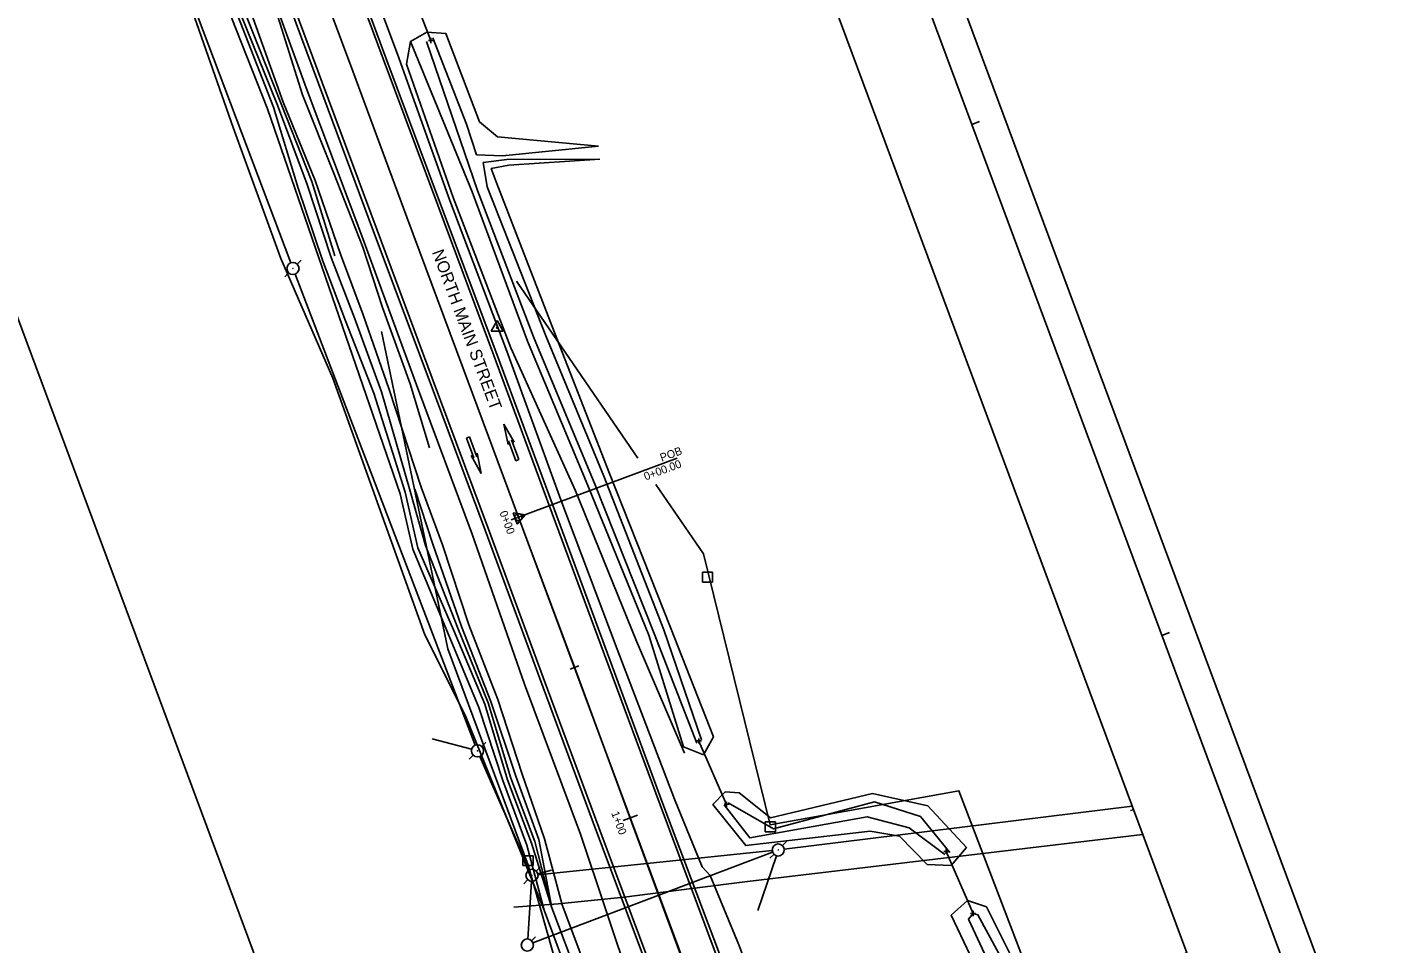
# Model space of a CAD drawing. Extents: x 1040172 to 1040822, y 1127790 to 1128580.
# Drawn here: x 1040398.7 to 1040821.5, y 1128002.5 to 1128288.4 of the extents above; entities that cross this region are included whole.
import ezdxf

# ---------------------------------------------------------------- set-up
doc = ezdxf.new("R2010")
doc.units = 0
for name, color, linetype in [('AC_P', 7, 'Continuous'), ('ACP_P', 7, 'Continuous'), ('ACSC_P_T', 7, 'Continuous'), ('ACSCT_P', 7, 'Continuous'), ('ACSR_P_T', 7, 'Continuous'), ('ACSRT_P', 7, 'Continuous'), ('CBP', 7, 'Continuous'), ('clip boundary', 7, 'Continuous'), ('DCP', 7, 'Continuous'), ('DD', 7, 'Continuous'), ('Default', 7, 'Continuous'), ('DELB', 7, 'Continuous'), ('DINV', 7, 'Continuous'), ('LABL', 7, 'Continuous'), ('LELB', 7, 'Continuous'), ('MHB', 7, 'Continuous'), ('MPM', 7, 'Continuous'), ('O_Details_Text Title and Subtitle Proposed_P_T', 7, 'Continuous'), ('PE', 7, 'Continuous'), ('RDU', 7, 'Continuous'), ('SHEET_BORDER', 7, 'Continuous'), ('SHEET_BORDER_CUT', 7, 'Continuous'), ('STPBY', 7, 'Continuous'), ('STSEW', 7, 'Continuous'), ('STSEY_P_T', 7, 'Continuous'), ('UEO', 7, 'Continuous'), ('UFO', 7, 'Continuous'), ('UP', 7, 'Continuous'), ('UPGW', 7, 'Continuous')]:
    doc.layers.add(name, color=color, linetype=linetype)

msp = doc.modelspace()

# ---------------------------------------------------------------- linework, layer by layer
at = {"layer": 'AC_P'}
msp.add_line((1040551.95, 1128135.59), (1040621.67, 1127948.13), dxfattribs=at)
at = {"layer": 'ACP_P'}
msp.add_circle((1040551.95, 1128135.59), 1.09, dxfattribs=at)
at = {"layer": 'ACSCT_P'}
msp.add_lwpolyline([(1040551.95, 1128135.59), (1040601.44, 1128153.99)], dxfattribs=at)
at = {"layer": 'ACSRT_P'}
for points in [[(1040554.2, 1128136.43), (1040549.7, 1128134.75)], [(1040570.73, 1128089.23), (1040568.03, 1128088.22)], [(1040589.06, 1128042.7), (1040584.56, 1128041.02)]]:
    msp.add_lwpolyline(points, dxfattribs=at)
at = {"layer": 'CBP'}
for points in [[(1040545.33, 1128196.91), (1040543.44, 1128193.64)], [(1040547.22, 1128193.64), (1040545.33, 1128196.91)], [(1040543.44, 1128193.64), (1040547.22, 1128193.64)]]:
    msp.add_lwpolyline(points, dxfattribs=at)
msp.add_circle((1040545.33, 1128194.73), 0.226, dxfattribs=at)
at = {"layer": 'clip boundary'}
for points in [[(1040584.48, 1128580.33), (1040821.52, 1127942.99), (1040409.12, 1127789.61), (1040172.08, 1128426.95)], [(1040311.42, 1128424.61), (1040504.79, 1127904.67), (1040760.34, 1127999.71), (1040566.96, 1128519.66)]]:
    msp.add_lwpolyline(points, close=True, dxfattribs=at)
at = {"layer": 'DCP'}
for p, q in [((1040516.73, 1128304.75), (1040524.64, 1128284.21)), ((1040608.2, 1128065.79), (1040616.86, 1128046.03)), ((1040685.33, 1128031.32), (1040693.73, 1128012))]:
    msp.add_line(p, q, dxfattribs=at)
at = {"layer": 'DD'}
msp.add_lwpolyline([(1040590.16, 1127936.41), (1040584.34, 1127954.8), (1040577.73, 1127972.42), (1040570.66, 1127991.71), (1040562.32, 1128013.81), (1040557.05, 1128034.44), (1040549.61, 1128054.25), (1040542.46, 1128077.69), (1040533.08, 1128100.98), (1040522.95, 1128126.72), (1040518.21, 1128143.72), (1040509.19, 1128174.67), (1040500.96, 1128197.49), (1040493.5, 1128216.61), (1040486.01, 1128239.31), (1040476.77, 1128264.06), (1040465.21, 1128292.91), (1040456.76, 1128312.61), (1040439.7, 1128341.45), (1040438.14, 1128345.77)], dxfattribs=at)
at = {"layer": 'Default'}
for points in [[(1040550.27, 1128136.98), (1040553.99, 1128136.35)], [(1040551.58, 1128133.44), (1040550.27, 1128136.98)], [(1040553.99, 1128136.35), (1040551.58, 1128133.44)]]:
    msp.add_lwpolyline(points, dxfattribs=at)
at = {"layer": 'DELB'}
for points in [[(1040609.63, 1128061.49), (1040603.4, 1128063.98), (1040592.64, 1128098.78), (1040573.56, 1128145.43), (1040554.77, 1128190.47), (1040537.48, 1128237.06), (1040518.28, 1128283.96), (1040523.35, 1128286.88)], [(1040576.87, 1128251.3), (1040545.4, 1128254.16), (1040539.75, 1128258.84), (1040529.3, 1128286.38), (1040523.35, 1128286.88)], [(1040576.87, 1128251.3), (1040546.97, 1128248.3), (1040538.91, 1128248.59), (1040535.75, 1128258.16), (1040525.25, 1128285.12)], [(1040607.56, 1128065.08), (1040594.26, 1128099.34), (1040575.72, 1128145.85), (1040556.63, 1128191.81), (1040539.21, 1128237.42), (1040523.27, 1128283.9)], [(1040609.07, 1128066.11), (1040597.28, 1128100.44), (1040578.59, 1128148.35), (1040560.51, 1128192.11), (1040542.16, 1128238.57), (1040540.96, 1128246.16), (1040548.27, 1128247.16), (1040577.32, 1128247.25)], [(1040609.63, 1128061.49), (1040612.73, 1128067.12), (1040599.32, 1128101.21), (1040580.32, 1128149.25), (1040563.23, 1128193.19), (1040545.04, 1128240.22), (1040543.44, 1128244.32), (1040548.97, 1128245.37), (1040577.32, 1128247.25)], [(1040686.92, 1128026.98), (1040679.43, 1128027.24), (1040670.73, 1128036.09), (1040661.62, 1128037.68), (1040622.81, 1128033.18), (1040612.58, 1128046.02), (1040616.37, 1128049.95)], [(1040686.92, 1128026.98), (1040691.64, 1128032.57), (1040679.65, 1128045.57), (1040662.38, 1128049.4), (1040630.53, 1128041.88), (1040620.82, 1128049.59), (1040616.37, 1128049.95)], [(1040684.93, 1128030.41), (1040673.79, 1128038.73), (1040660.7, 1128042.19), (1040624.06, 1128035.63), (1040616.15, 1128045.92)], [(1040686.46, 1128031.07), (1040677.28, 1128042.28), (1040663, 1128046.83), (1040631.45, 1128038.39), (1040617.38, 1128046.55)], [(1040702.66, 1127978.26), (1040686.91, 1128011.53), (1040691.97, 1128016.01), (1040697.9, 1128014.08), (1040712.9, 1127984.14), (1040713.54, 1127982.3)], [(1040706.5, 1127979.69), (1040692.31, 1128010.21), (1040693.73, 1128012), (1040695.25, 1128011.56), (1040710.7, 1127983.05), (1040711.25, 1127981.45)]]:
    msp.add_lwpolyline(points, dxfattribs=at)
at = {"layer": 'DINV'}
for p, q in [((1040524.66, 1128284.25), (1040524.66, 1128285.04)), ((1040524.66, 1128284.25), (1040523.87, 1128284.25)), ((1040524.66, 1128284.25), (1040525.44, 1128284.25)), ((1040524.66, 1128284.25), (1040524.66, 1128283.46)), ((1040608.22, 1128065.82), (1040607.43, 1128065.82)), ((1040608.22, 1128065.82), (1040608.22, 1128066.61)), ((1040608.22, 1128065.82), (1040609, 1128065.82)), ((1040608.22, 1128065.82), (1040608.22, 1128065.04)), ((1040616.87, 1128046.06), (1040616.09, 1128046.06)), ((1040616.87, 1128046.06), (1040616.87, 1128046.85)), ((1040616.87, 1128046.06), (1040617.66, 1128046.06)), ((1040616.87, 1128046.06), (1040616.87, 1128045.28)), ((1040685.34, 1128031.35), (1040684.56, 1128031.35)), ((1040685.34, 1128031.35), (1040685.34, 1128032.14)), ((1040685.34, 1128031.35), (1040686.13, 1128031.35)), ((1040685.34, 1128031.35), (1040685.34, 1128030.57)), ((1040693.73, 1128012), (1040692.94, 1128012)), ((1040693.73, 1128012), (1040693.73, 1128012.79)), ((1040693.73, 1128012), (1040694.52, 1128012)), ((1040693.73, 1128012), (1040693.73, 1128011.21))]:
    msp.add_line(p, q, dxfattribs=at)
at = {"layer": 'LABL'}
msp.add_lwpolyline([(1040425.91, 1128368.18), (1040444.53, 1128309.71), (1040463.02, 1128257.15), (1040477.81, 1128216.23), (1040494.07, 1128178.95), (1040522.79, 1128098.94), (1040535.3, 1128073.89), (1040559.97, 1128013.01), (1040568.12, 1127991.17), (1040574.76, 1127971.48), (1040581.61, 1127953.82), (1040587.68, 1127935.49)], dxfattribs=at)
at = {"layer": 'LELB'}
for points in [[(1040524.19, 1128157.24), (1040518.18, 1128177.19), (1040509.58, 1128200.97), (1040503.44, 1128219.77), (1040494.26, 1128243.13), (1040484.62, 1128267.31), (1040475.77, 1128295.4), (1040467.07, 1128317.96), (1040457.98, 1128329.2), (1040449.47, 1128345.43), (1040446.95, 1128352.21), (1040444.14, 1128359.62), (1040438.48, 1128377.55), (1040433.46, 1128409.8), (1040426.84, 1128428.17), (1040419.78, 1128446.21), (1040413.29, 1128462.5)], [(1040562.32, 1128013.81), (1040556.06, 1128033.92), (1040548.57, 1128053.68), (1040541.49, 1128077.3), (1040531.67, 1128100.43), (1040520.61, 1128126.06), (1040516.58, 1128143.34), (1040506.89, 1128174.28), (1040498.03, 1128196.84), (1040490.79, 1128215.69), (1040483.27, 1128238.22), (1040475.53, 1128263.46), (1040464.25, 1128292.43), (1040455.52, 1128312.02), (1040438.72, 1128340.45), (1040438.45, 1128340.97), (1040437.13, 1128341.43), (1040434.71, 1128340.72), (1040422.09, 1128339.34)], [(1040494.64, 1128217.07), (1040487.54, 1128240.23), (1040477.97, 1128264.47), (1040466.44, 1128293.63), (1040458.2, 1128313.37), (1040440.59, 1128340.8)], [(1040554.52, 1128033.3), (1040547.08, 1128053.47), (1040539.58, 1128076.27), (1040529.8, 1128099.73), (1040518.96, 1128125.65), (1040515.08, 1128142.88), (1040473.71, 1128262.92), (1040462.39, 1128291.59), (1040453.72, 1128311.36), (1040437.26, 1128336.15), (1040435.49, 1128337), (1040422.35, 1128335.42)], [(1040593.2, 1127937.55), (1040587.34, 1127956.62), (1040581.09, 1127973.78), (1040573.86, 1127992.53), (1040565.61, 1128014.66), (1040560.09, 1128035.33), (1040553.1, 1128055.45), (1040545.54, 1128078.74), (1040536.49, 1128101.98), (1040528.25, 1128126.98), (1040521.57, 1128144.94), (1040511.66, 1128175.43), (1040503.47, 1128198.65), (1040496.47, 1128217.58), (1040488.54, 1128240.6), (1040478.6, 1128264.98), (1040468.18, 1128294)], [(1040603.73, 1128062.03), (1040588.8, 1128096.96), (1040569.72, 1128143.77), (1040549.57, 1128188.37), (1040531.56, 1128235.26), (1040517.07, 1128276.83), (1040518.28, 1128283.96)], [(1040562.32, 1128013.81), (1040558.32, 1128035.07), (1040551.1, 1128054.81), (1040543.36, 1128078.15), (1040534.21, 1128101.46), (1040525.24, 1128127.18), (1040519.65, 1128144.29)], [(1040587.68, 1127935.49), (1040581.61, 1127953.82), (1040574.76, 1127971.48), (1040568.12, 1127991.17), (1040559.97, 1128013.01), (1040554.52, 1128033.3)]]:
    msp.add_lwpolyline(points, dxfattribs=at)
at = {"layer": 'MHB'}
for points in [[(1040551.37, 1128209.2), (1040589.17, 1128154.02)], [(1040581.63, 1127933.24), (1040555, 1128027.07), (1040529.93, 1128094.57), (1040509.19, 1128193.54)], [(1040594.84, 1128145.74), (1040609.62, 1128124.16), (1040630.41, 1128039.61), (1040689.32, 1128050.28), (1040715.1, 1127982.88)]]:
    msp.add_lwpolyline(points, dxfattribs=at)
at = {"layer": 'MPM'}
for p, q in [((1040609.29, 1128115.34), (1040609.29, 1128118.4)), ((1040609.29, 1128118.4), (1040612.44, 1128118.4)), ((1040612.44, 1128118.4), (1040612.44, 1128115.34)), ((1040612.44, 1128115.34), (1040609.29, 1128115.34)), ((1040628.91, 1128037.49), (1040628.91, 1128040.55)), ((1040628.91, 1128040.55), (1040632.07, 1128040.55)), ((1040632.07, 1128040.55), (1040632.07, 1128037.49)), ((1040632.07, 1128037.49), (1040628.91, 1128037.49)), ((1040553.35, 1128026.92), (1040553.35, 1128029.99)), ((1040553.35, 1128029.99), (1040556.5, 1128029.99)), ((1040556.5, 1128029.99), (1040556.5, 1128026.92)), ((1040556.5, 1128026.92), (1040553.35, 1128026.92))]:
    msp.add_line(p, q, dxfattribs=at)
at = {"layer": 'O_Details_Text Title and Subtitle Proposed_P_T'}
for p, q in [((1040548.72, 1128158.26), (1040547.42, 1128164.61)), ((1040550.59, 1128158.96), (1040547.42, 1128164.61)), ((1040536.18, 1128160.42), (1040536.15, 1128160.41)), ((1040536.18, 1128160.41), (1040536.16, 1128160.4)), ((1040549.77, 1128159.72), (1040550.59, 1128158.96)), ((1040537.19, 1128154.83), (1040540.36, 1128149.18)), ((1040538.01, 1128154.06), (1040537.19, 1128154.83)), ((1040539.07, 1128155.52), (1040540.36, 1128149.18)), ((1040551.6, 1128153.38), (1040551.63, 1128153.39)), ((1040551.61, 1128153.36), (1040551.63, 1128153.37))]:
    msp.add_line(p, q, dxfattribs=at)
at = {"layer": 'PE'}
for points in [[(1040439.24, 1128472.16), (1040441.33, 1128466.57), (1040458.94, 1128419.35), (1040476.26, 1128371.77), (1040493.04, 1128326.48), (1040510.61, 1128278.87), (1040527.62, 1128233.22), (1040545.23, 1128186.41), (1040562.42, 1128139.9), (1040579.67, 1128093.09), (1040596.97, 1128046.17), (1040614.6, 1127999.47), (1040632.03, 1127952.66), (1040632.25, 1127952.07)], [(1040611.22, 1127944.25), (1040611.04, 1127944.71), (1040593.69, 1127991.31), (1040575.95, 1128038.43), (1040558.63, 1128085.25), (1040541.53, 1128131.54), (1040524.14, 1128178.42), (1040506.77, 1128224.73), (1040489.58, 1128270.79), (1040472.04, 1128318.16), (1040455.43, 1128363.98), (1040438.41, 1128410.32), (1040420.58, 1128458.47), (1040418.37, 1128464.39)]]:
    msp.add_lwpolyline(points, dxfattribs=at)
at = {"layer": 'RDU'}
for points in [[(1040442.34, 1128473.31), (1040444.42, 1128467.6), (1040461.41, 1128420.47), (1040479.69, 1128373.54), (1040484.11, 1128363.91), (1040487.49, 1128353.45), (1040496.23, 1128327.89), (1040514.27, 1128279.94), (1040530.58, 1128234.37), (1040548.36, 1128187.4), (1040565.14, 1128141.04), (1040582.73, 1128094.4), (1040600.59, 1128047.69), (1040609.21, 1128026.55), (1040611.78, 1128023.8), (1040620.64, 1128002.21), (1040638.45, 1127955.04), (1040638.78, 1127954.5)], [(1040600.82, 1127940.38), (1040598.84, 1127946.51), (1040597.95, 1127949.62), (1040587.15, 1127989.28), (1040571.28, 1128036.76), (1040553.79, 1128083.5), (1040537.46, 1128130.34), (1040520.2, 1128176.84), (1040503.11, 1128223.36), (1040485.75, 1128269.45), (1040468.45, 1128317.03), (1040451.55, 1128362.66), (1040435.14, 1128409.38), (1040417.07, 1128457.26), (1040414.87, 1128463.09)]]:
    msp.add_lwpolyline(points, dxfattribs=at)
at = {"layer": 'SHEET_BORDER'}
for p, q in [((1040693.34, 1128258.07), (1040695.68, 1128258.94)), ((1040752.6, 1128098.73), (1040754.94, 1128099.6))]:
    msp.add_line(p, q, dxfattribs=at)
msp.add_lwpolyline([(1040412.42, 1127817.51), (1040409.2, 1127818.98), (1040191.33, 1128404.77), (1040192.81, 1128407.99), (1040581.19, 1128552.44), (1040584.4, 1128550.96), (1040802.27, 1127965.17), (1040800.8, 1127961.95)], close=True, dxfattribs=at)
at = {"layer": 'SHEET_BORDER_CUT'}
msp.add_lwpolyline([(1040172.08, 1128426.95), (1040409.12, 1127789.61), (1040821.52, 1127942.99), (1040584.48, 1128580.33)], close=True, dxfattribs=at)
at = {"layer": 'STPBY'}
msp.add_lwpolyline([(1040621.67, 1127948.13), (1040621.55, 1127948.45), (1040603.98, 1127995.3), (1040586.61, 1128042.26), (1040569.27, 1128089.08), (1040551.95, 1128135.59), (1040534.57, 1128182.32), (1040517.18, 1128229.1), (1040500.26, 1128274.64), (1040482.6, 1128322.04), (1040465.84, 1128367.81), (1040448.53, 1128414.76), (1040430.74, 1128462.77), (1040428.7, 1128468.23)], dxfattribs=at)
at = {"layer": 'STSEW'}
for points in [[(1040438.27, 1128471.79), (1040440.35, 1128466.17), (1040457.9, 1128418.91), (1040475.34, 1128371.42), (1040492.13, 1128326.1), (1040509.73, 1128278.49), (1040526.79, 1128232.92), (1040544.25, 1128186.02), (1040561.46, 1128139.5), (1040578.77, 1128092.69), (1040596.13, 1128045.88), (1040613.59, 1127999.12), (1040631.02, 1127952.26), (1040631.23, 1127951.69)], [(1040612.07, 1127944.56), (1040611.89, 1127945.04), (1040594.53, 1127991.69), (1040577, 1128038.8), (1040559.65, 1128085.64), (1040542.56, 1128131.85), (1040525.02, 1128178.93), (1040507.92, 1128225.11), (1040490.75, 1128271.15), (1040473.24, 1128318.19), (1040456.29, 1128364.36), (1040439.27, 1128410.63), (1040421.37, 1128458.89), (1040419.2, 1128464.7)]]:
    msp.add_lwpolyline(points, dxfattribs=at)
at = {"layer": 'STSEY_P_T'}
for p, q in [((1040550.59, 1128158.96), (1040547.42, 1128164.61)), ((1040547.42, 1128164.61), (1040548.72, 1128158.26)), ((1040536.65, 1128160.6), (1040535.71, 1128160.25)), ((1040535.71, 1128160.25), (1040538.01, 1128154.06)), ((1040535.71, 1128160.25), (1040538.01, 1128154.06)), ((1040536.65, 1128160.6), (1040538.95, 1128154.41)), ((1040538.95, 1128154.41), (1040536.65, 1128160.6)), ((1040548.84, 1128159.37), (1040548.72, 1128158.26)), ((1040548.72, 1128158.26), (1040548.84, 1128159.37)), ((1040551.14, 1128153.19), (1040548.84, 1128159.37)), ((1040548.84, 1128159.37), (1040551.14, 1128153.19)), ((1040552.08, 1128153.53), (1040549.77, 1128159.72)), ((1040552.08, 1128153.53), (1040549.77, 1128159.72)), ((1040549.77, 1128159.72), (1040550.59, 1128158.96)), ((1040538.01, 1128154.06), (1040537.19, 1128154.83)), ((1040537.19, 1128154.83), (1040540.36, 1128149.18)), ((1040538.95, 1128154.41), (1040539.07, 1128155.52)), ((1040539.07, 1128155.52), (1040538.95, 1128154.41)), ((1040540.36, 1128149.18), (1040539.07, 1128155.52)), ((1040551.14, 1128153.19), (1040552.08, 1128153.53))]:
    msp.add_line(p, q, dxfattribs=at)
for points in [[(1040536.65, 1128160.6), (1040536.18, 1128160.42), (1040535.71, 1128160.25)], [(1040551.14, 1128153.19), (1040551.61, 1128153.36), (1040552.08, 1128153.53)]]:
    msp.add_lwpolyline(points, dxfattribs=at)
at = {"layer": 'UEO'}
for points in [[(1040410.74, 1128400.93), (1040480.95, 1128214.9)], [(1040482.29, 1128211.36), (1040538.49, 1128064.48)], [(1040555.4, 1128025.62), (1040539.92, 1128060.98)], [(1040634.85, 1128032.05), (1040743.3, 1128045.52)], [(1040558.04, 1128024.08), (1040631.09, 1128031.62)], [(1040556.48, 1128002.83), (1040631.2, 1128031.14)], [(1040554.84, 1128004.04), (1040556.04, 1128022)]]:
    msp.add_lwpolyline(points, dxfattribs=at)
at = {"layer": 'UFO'}
msp.add_lwpolyline([(1040550.53, 1128013.94), (1040564.33, 1128015), (1040584.89, 1128017.11), (1040605.98, 1128019.76), (1040623.41, 1128022.01), (1040746.6, 1128036.66)], dxfattribs=at)
at = {"layer": 'UP'}
for p, q in [((1040481.68, 1128213.13), (1040481.56, 1128213.13)), ((1040481.62, 1128213.19), (1040481.62, 1128213.07)), ((1040482.95, 1128214.47), (1040484.2, 1128215.73)), ((1040480.28, 1128211.79), (1040479.04, 1128210.53)), ((1040540.5, 1128064.06), (1040541.75, 1128065.31)), ((1040537.83, 1128061.37), (1040536.58, 1128060.12)), ((1040539.23, 1128062.72), (1040539.1, 1128062.71)), ((1040539.16, 1128062.78), (1040539.16, 1128062.65)), ((1040633.04, 1128031.81), (1040632.91, 1128031.81)), ((1040632.97, 1128031.88), (1040632.97, 1128031.75)), ((1040634.31, 1128033.16), (1040635.55, 1128034.41)), ((1040631.64, 1128030.47), (1040630.39, 1128029.22)), ((1040556.22, 1128023.89), (1040556.1, 1128023.89)), ((1040556.16, 1128023.95), (1040556.16, 1128023.83)), ((1040557.49, 1128025.23), (1040558.74, 1128026.49)), ((1040554.83, 1128022.55), (1040553.58, 1128021.29)), ((1040556.05, 1128003.5), (1040557.29, 1128004.75))]:
    msp.add_line(p, q, dxfattribs=at)
for centre in [(1040481.62, 1128213.13), (1040539.16, 1128062.71), (1040632.97, 1128031.81), (1040556.16, 1128023.89), (1040554.71, 1128002.16)]:
    msp.add_circle(centre, 1.89, dxfattribs=at)
at = {"layer": 'UPGW'}
for points in [[(1040525.04, 1128066.47), (1040537.34, 1128063.2)], [(1040742.79, 1128044.14), (1040743.76, 1128044.3)], [(1040626.56, 1128012.89), (1040632.37, 1128030.02)], [(1040562.25, 1128025.5), (1040557.99, 1128024.37)]]:
    msp.add_lwpolyline(points, dxfattribs=at)

# ---------------------------------------------------------------- texts
at = {"layer": 'ACSC_P_T'}
for s, p in [('POB', (1040596.64, 1128152.88)), ('0+00.00', (1040591.62, 1128147.01))]:
    msp.add_text(s, height=2.496, rotation=20.4011, dxfattribs=at).set_placement(p)
at = {"layer": 'ACSR_P_T'}
for s, p in [('0+00', (1040545.98, 1128137.06)), ('1+00', (1040580.83, 1128043.33))]:
    msp.add_text(s, height=2.496, rotation=290.4011, dxfattribs=at).set_placement(p)
at = {"layer": 'O_Details_Text Title and Subtitle Proposed_P_T'}
msp.add_text('NORTH MAIN STREET', height=3.7536, rotation=290.4011, dxfattribs=at).set_placement((1040524.92, 1128218.26))

doc.saveas('drawing.dxf')
